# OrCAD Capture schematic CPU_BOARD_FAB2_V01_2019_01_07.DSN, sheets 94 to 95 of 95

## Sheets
94 020 BDX-DE PCIE CPU/PCH: size B
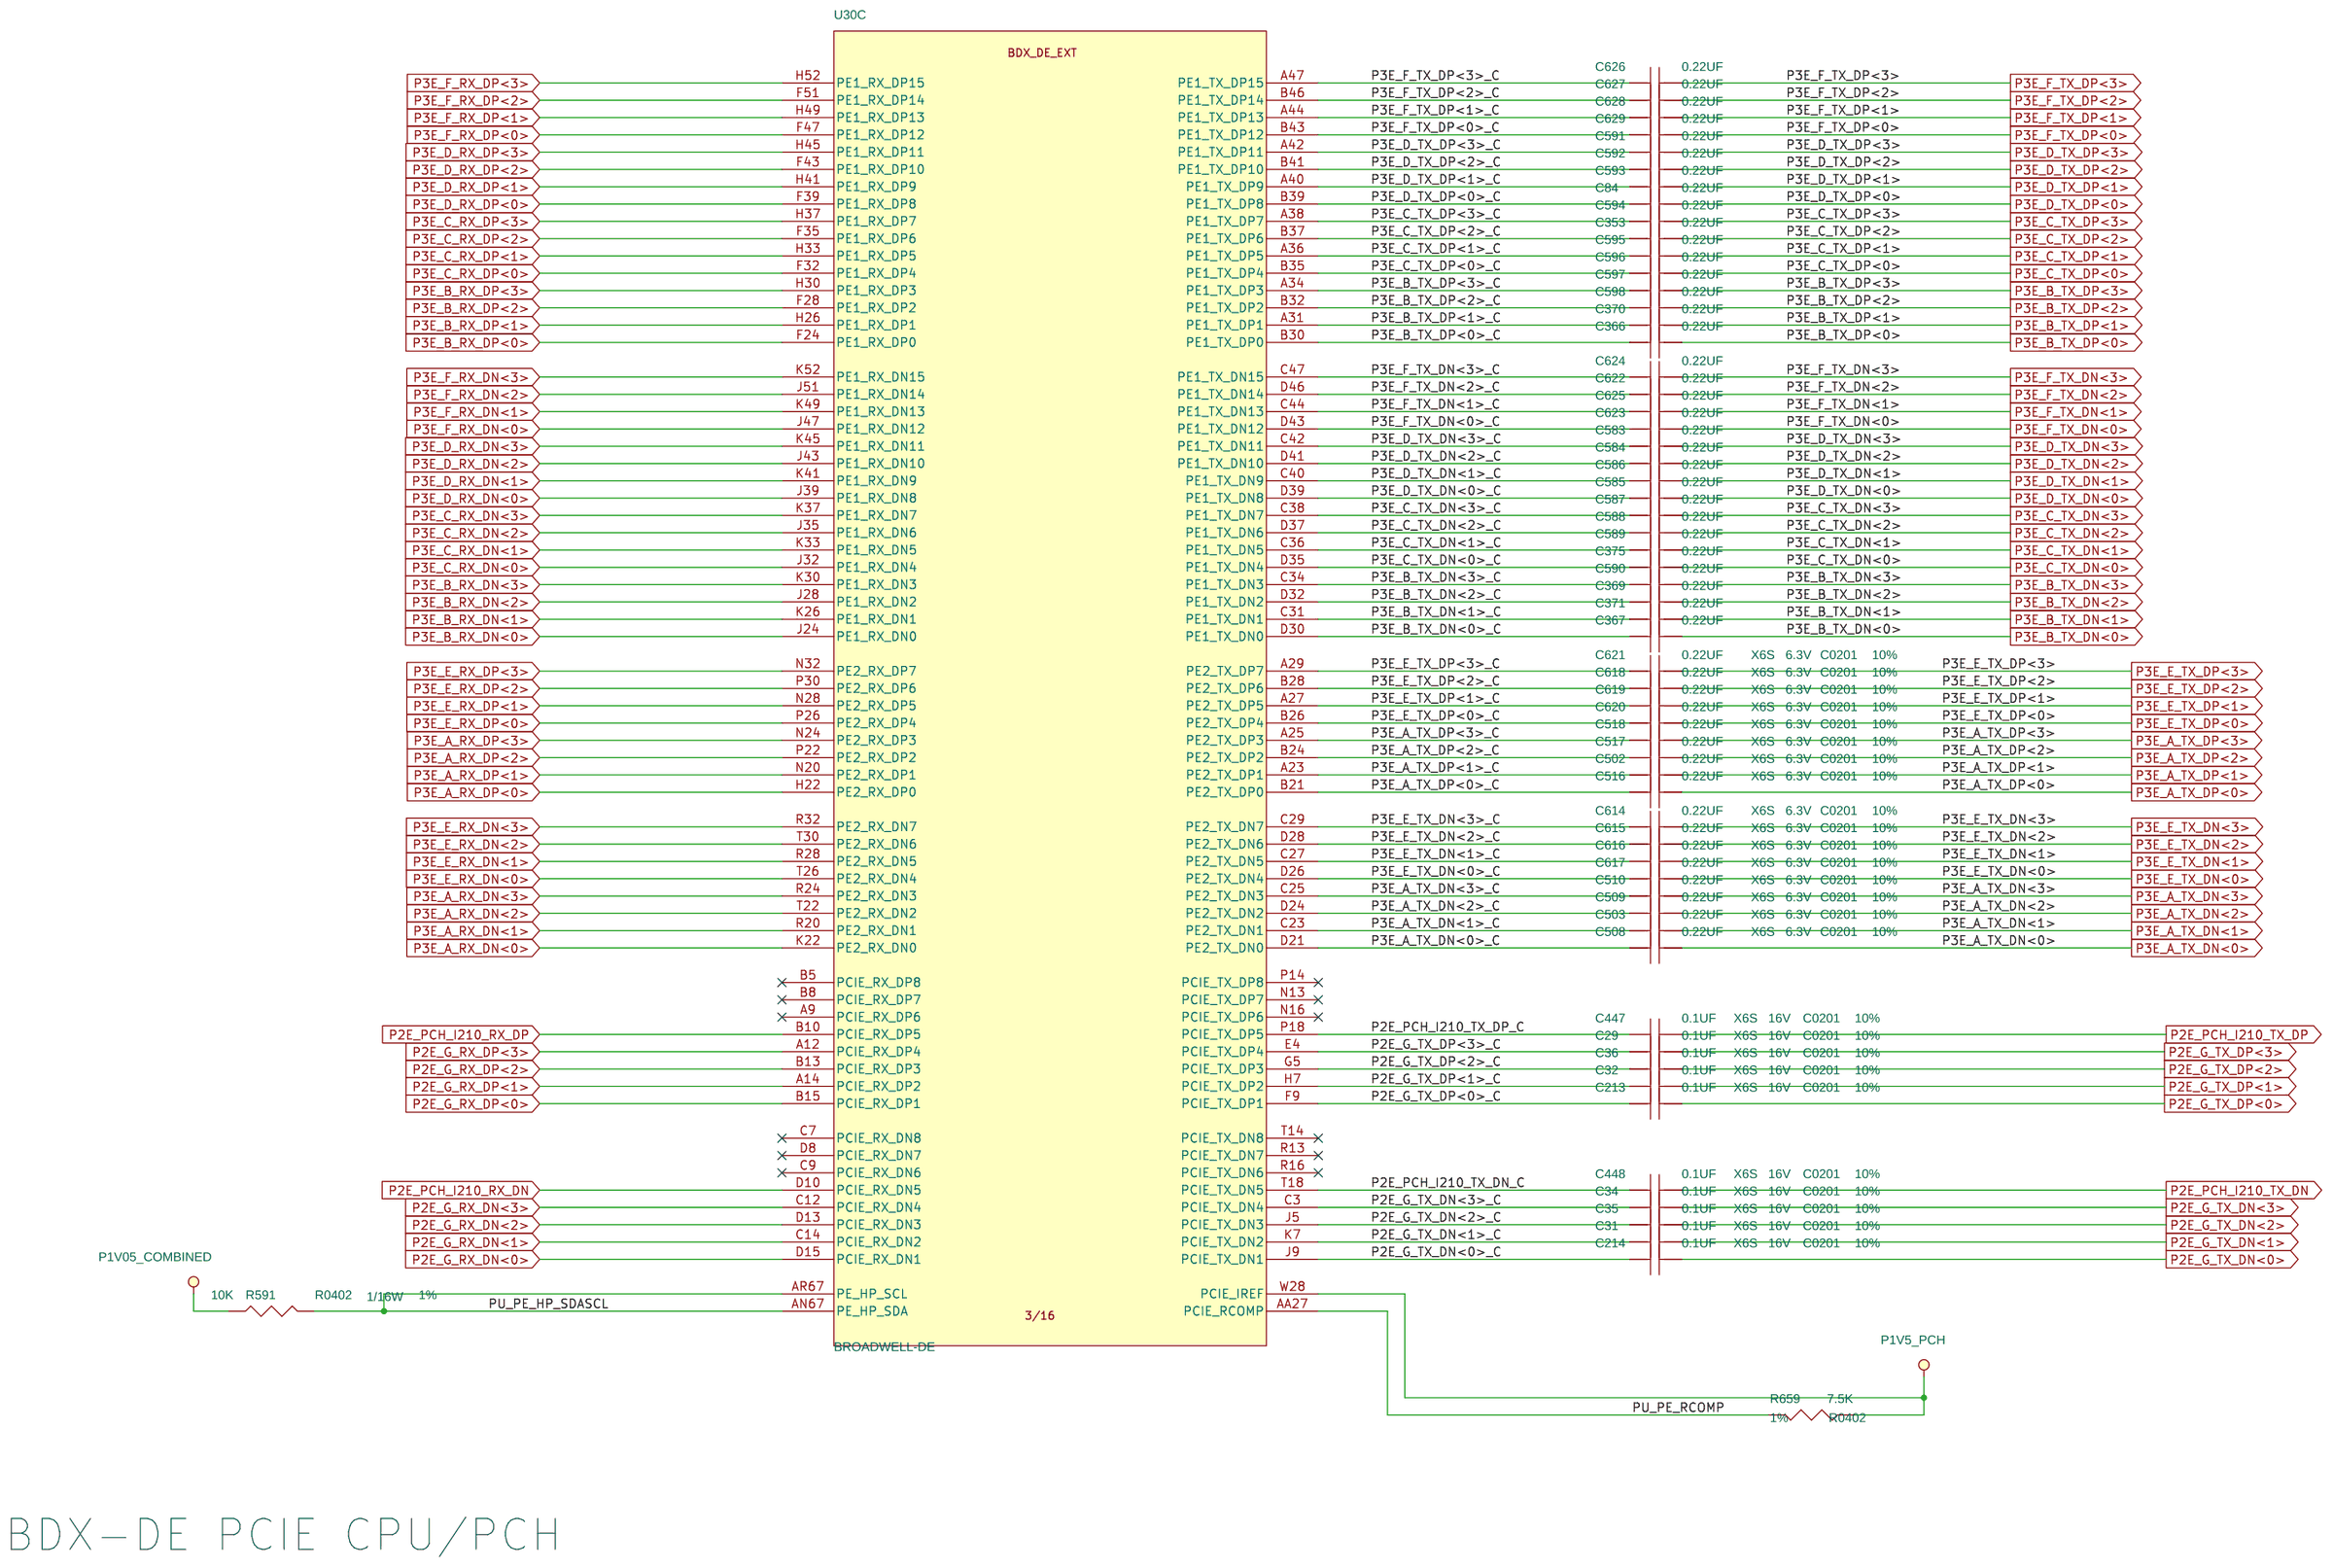
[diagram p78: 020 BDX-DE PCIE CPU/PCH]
95 010 INTERRUPT/ERROR ESCALATION
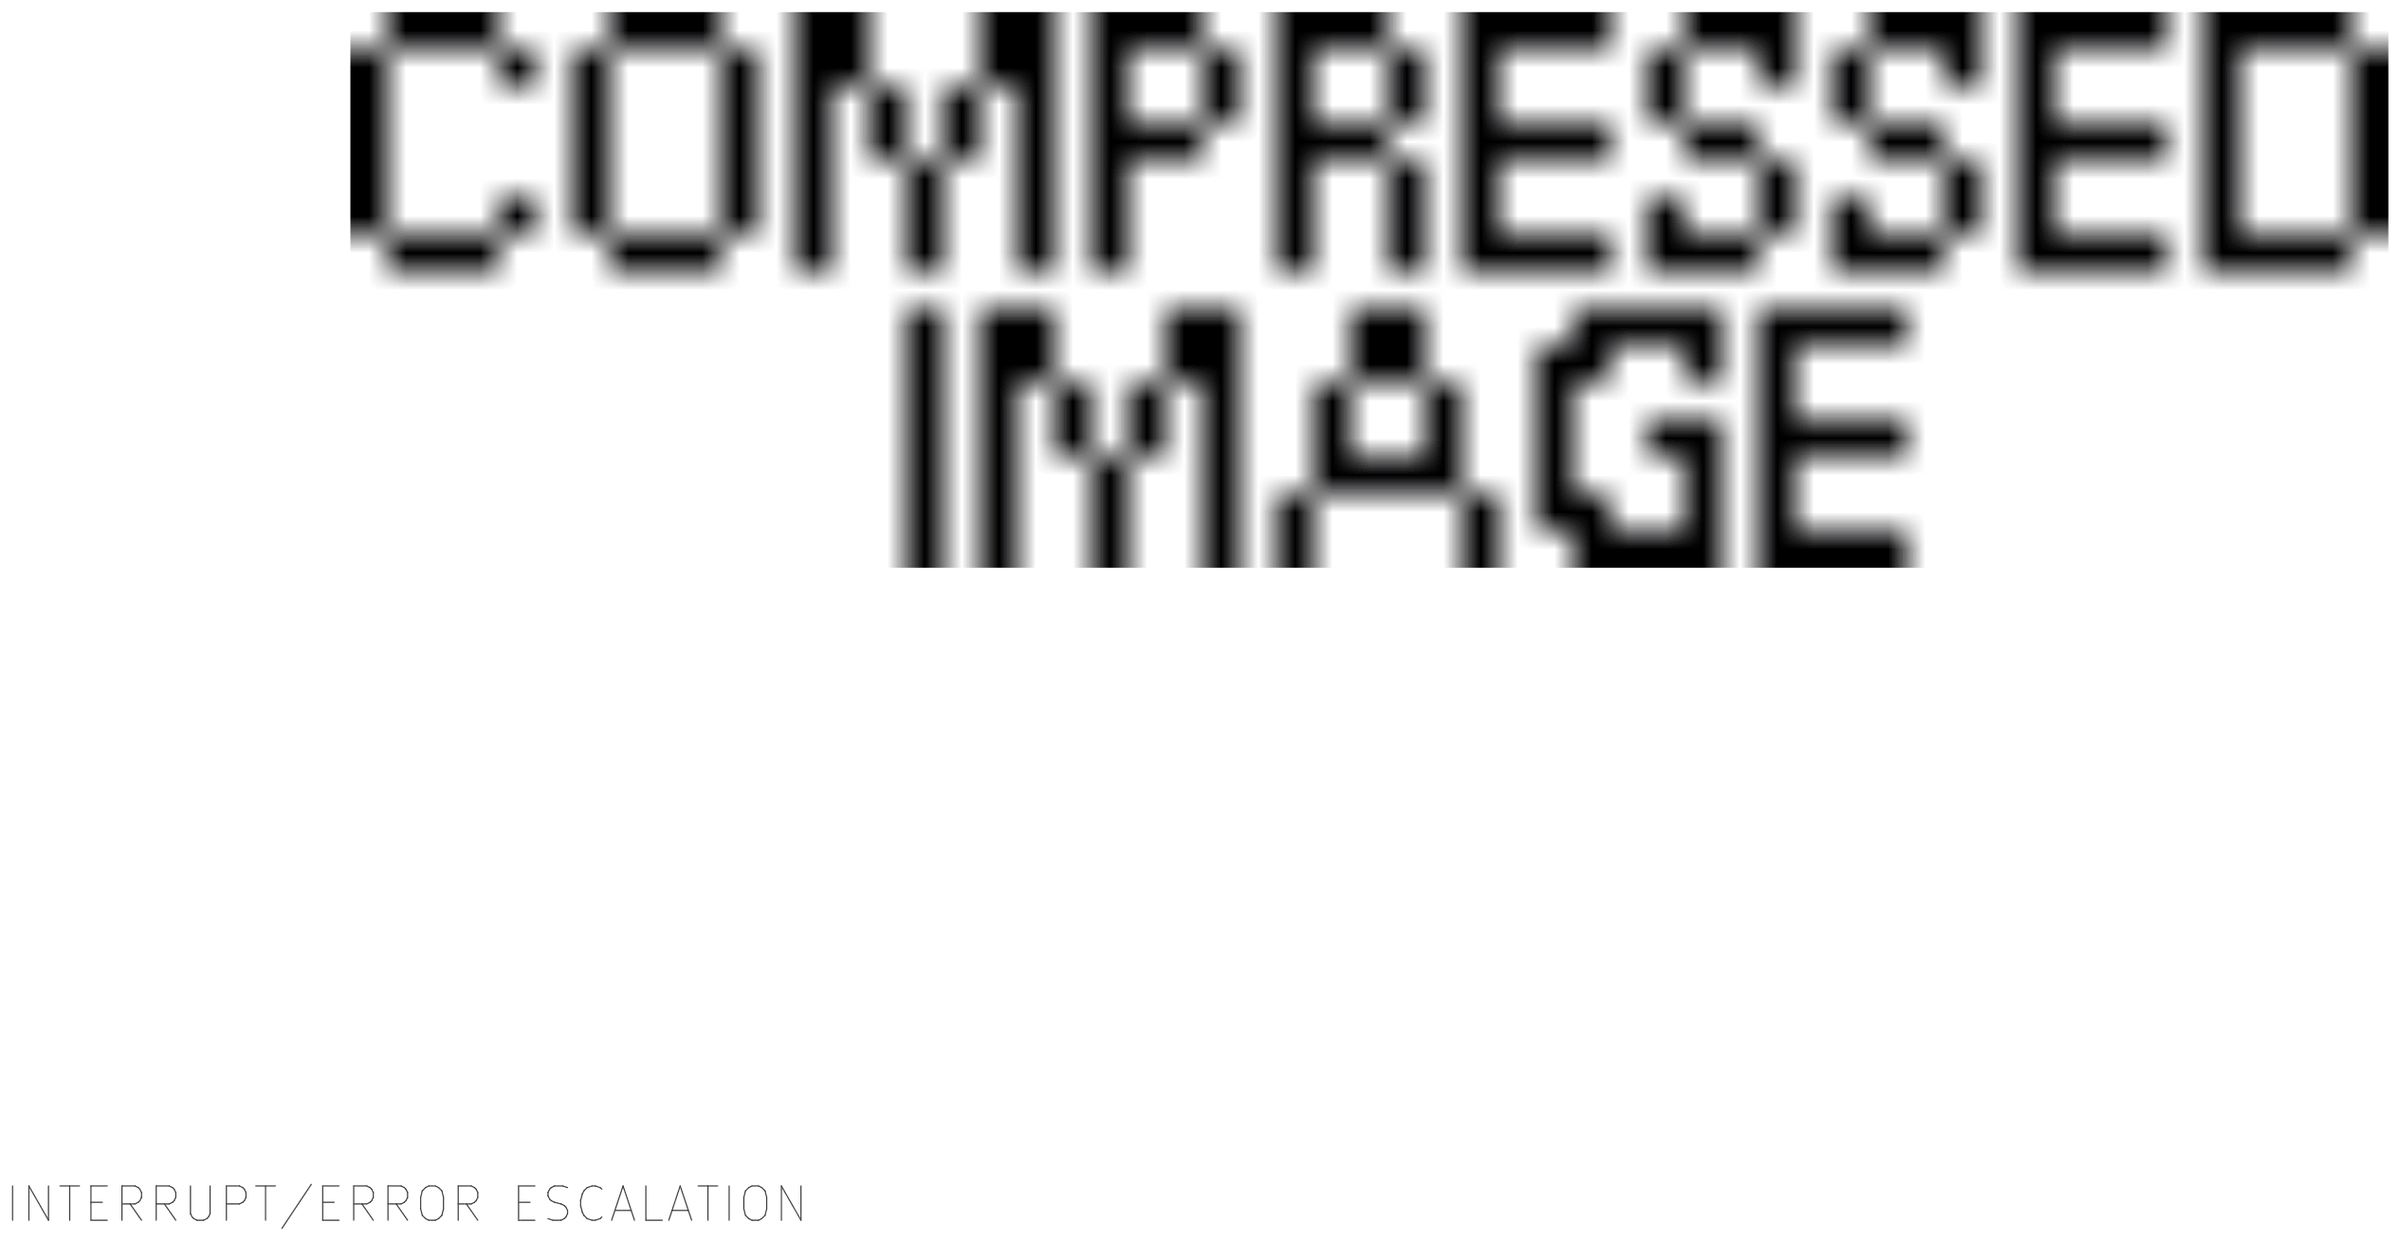
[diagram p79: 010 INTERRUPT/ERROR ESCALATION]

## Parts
sheet 020 BDX-DE PCIE CPU/PCH
C29  0.1UF  [C0201]
C31  0.1UF  [C0201]
C32  0.1UF  [C0201]
C34  0.1UF  [C0201]
C35  0.1UF  [C0201]
C36  0.1UF  [C0201]
C84  0.22UF  [C0201]
C213  0.1UF  [C0201]
C214  0.1UF  [C0201]
C353  0.22UF  [C0201]
C366  0.22UF  [C0201]
C367  0.22UF  [C0201]
C369  0.22UF  [C0201]
C370  0.22UF  [C0201]
C371  0.22UF  [C0201]
C375  0.22UF  [C0201]
C447  0.1UF  [C0201]
C448  0.1UF  [C0201]
C502  0.22UF  [C0201]
C503  0.22UF  [C0201]
C508  0.22UF  [C0201]
C509  0.22UF  [C0201]
C510  0.22UF  [C0201]
C516  0.22UF  [C0201]
C517  0.22UF  [C0201]
C518  0.22UF  [C0201]
C583  0.22UF  [C0201]
C584  0.22UF  [C0201]
C585  0.22UF  [C0201]
C586  0.22UF  [C0201]
C587  0.22UF  [C0201]
C588  0.22UF  [C0201]
C589  0.22UF  [C0201]
C590  0.22UF  [C0201]
C591  0.22UF  [C0201]
C592  0.22UF  [C0201]
C593  0.22UF  [C0201]
C594  0.22UF  [C0201]
C595  0.22UF  [C0201]
C596  0.22UF  [C0201]
C597  0.22UF  [C0201]
C598  0.22UF  [C0201]
C614  0.22UF  [C0201]
C615  0.22UF  [C0201]
C616  0.22UF  [C0201]
C617  0.22UF  [C0201]
C618  0.22UF  [C0201]
C619  0.22UF  [C0201]
C620  0.22UF  [C0201]
C621  0.22UF  [C0201]
C622  0.22UF  [C0201]
C623  0.22UF  [C0201]
C624  0.22UF  [C0201]
C625  0.22UF  [C0201]
C626  0.22UF  [C0201]
C627  0.22UF  [C0201]
C628  0.22UF  [C0201]
C629  0.22UF  [C0201]
R591  10K  [R0402]
R659  7.5K  [R0402]
sheet 023 BDX-DE SATA, USB2, USB3
U30  BROADWELL-DE  [BGA1667]  (sections A,B,C,D,E,F,G,H,I,J,K,L,M,N,O,P)

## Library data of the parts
C29 C31 C32 C34-C36 C213 C214 C447 C448 = CAP_NP: CAP CHIP 0.1UF 16V(+-10%,X6S,0201); CLASS: DISCRETE; CMPLS_LVL: EP(V1); Data: TAY_EMK063AC6104KP.pdf; From_pj: S2P-SEAN; Lifecycle: Comp-Approve; MATERIAL: X6S; Manuf_PN: EMK063AC6104KP-F; Manuf_name: TAIYO YUDEN CO.,LTD; Manuftr: TAY; Part_Type: *LF_C0201; RD_CMPLS_LVL: EP(V1); TOLERANCE: 10%; VOLTAGE: 16V; fp_ECN: DCN-all 0201 RCL part.doc
C84 C353 C366 C367 C369-C371 C375 C502 C503 C508-C510 C516-C518 C583-C598 C614-C629 = CAP_NP: CAP CHIP 0.22UF 6.3V(+-10%,X6S,0201); CLASS: DISCRETE; CMPLS_LVL: EP(V1); Data: MUR_LF_CAPSERIES_19JUN2012.pdf; From_pj: MF1-EDDIE; Lifecycle: Comp-Approve; MATERIAL: X6S; Manuf_PN: GRM033C80J224K; Manuf_name: MURATA ERIE N.A. INC TAIWAN BRANCH Okayama Murata Mfg.Co.,Ltd.Wakura Murata Mfg.; Manuftr: MUR; Part_Type: *LF_C0201; RD_CMPLS_LVL: EP(V1); TOLERANCE: 10%; VOLTAGE: 6.3V; fp_ECN: DCN-all 0201 RCL part.doc
R591 = R: RES CHIP 10K 1/16W +-1% (0402); CLASS: DISCRETE; CMPLS_LVL: EP; Data: WTC_LF_WR SERIES.pdf; From_pj: S82; Lifecycle: Comp-Approve; MATERIAL: CHIP; Manuf_PN: RR0510S-103-FN; Manuf_name: CYNTEC CO.. LTD.; Manuftr: CYN; Part_Type: *LF_Resistor; Status: Preferred; TOLERANCE: 1%; WATTAGE: 1/16W; fp_ECN: 0402 SERIES_LL34.xls
R659 = R: RES CHIP 7.5K 1/16W +-1% (0402); CLASS: DISCRETE; CMPLS_LVL: EP; Data: WTC_LF_WR SERIES-4.pdf; From_pj: S93-MARTIN; MATERIAL: CHIP; Manuf_PN: WR04X7501FTL; Manuf_name: WALSIN TECHNOLOGY CORPORATION; Manuftr: WTC; Part_Type: *LF_Resistor; TOLERANCE: 1%; WATTAGE: 1/16W; fp_ECN: 0402 SERIES_LL34.xls
U30 = BROADWELLDE: CPU(1667P)Broadwell-DE (FCBGA); CLASS: IC; Data: INT_Broadwell-DE_REV0_75.pdf; From_pj: S1M-MANSON; MATERIAL: IC; Manuf_name: INTEGRATED DEVICE TECHNOLOGY,INC.; Manuftr: INT; Part_Type: Tmp; Color: Default; Location X-Coordinate: 0; Location Y-Coordinate: 0; Power Pins Visible: False; Primitive: DEFAULT

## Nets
P1V05_COMBINED: R591.1 ; also on sheet 1 3 4 16 18 19 41 42 45 47 48 50 51 52 54 55 56 63 71 74 75 79 84 92
P1V5_PCH: R659.1 U30.W28(PCIE_IREF) ; also on sheet 31 46 47 49 52
P2E_G_RX_DN<0>: U30.D15(PCIE_RX_DN1) ; also on sheet 13
P2E_G_RX_DN<1>: U30.C14(PCIE_RX_DN2) ; also on sheet 13
P2E_G_RX_DN<2>: U30.D13(PCIE_RX_DN3) ; also on sheet 13
P2E_G_RX_DN<3>: U30.C12(PCIE_RX_DN4) ; also on sheet 13
P2E_G_RX_DP<0>: U30.B15(PCIE_RX_DP1) ; also on sheet 13
P2E_G_RX_DP<1>: U30.A14(PCIE_RX_DP2) ; also on sheet 13
P2E_G_RX_DP<2>: U30.B13(PCIE_RX_DP3) ; also on sheet 13
P2E_G_RX_DP<3>: U30.A12(PCIE_RX_DP4) ; also on sheet 13
P2E_G_TX_DN<0>: C214.2 ; also on sheet 13
P2E_G_TX_DN<0>_C: C214.1 U30.J9(PCIE_TX_DN1)
P2E_G_TX_DN<1>: C31.2 ; also on sheet 13
P2E_G_TX_DN<1>_C: C31.1 U30.K7(PCIE_TX_DN2)
P2E_G_TX_DN<2>: C35.2 ; also on sheet 13
P2E_G_TX_DN<2>_C: C35.1 U30.J5(PCIE_TX_DN3)
P2E_G_TX_DN<3>: C34.2 ; also on sheet 13
P2E_G_TX_DN<3>_C: C34.1 U30.C3(PCIE_TX_DN4)
P2E_G_TX_DP<0>: C213.2 ; also on sheet 13
P2E_G_TX_DP<0>_C: C213.1 U30.F9(PCIE_TX_DP1)
P2E_G_TX_DP<1>: C32.2 ; also on sheet 13
P2E_G_TX_DP<1>_C: C32.1 U30.H7(PCIE_TX_DP2)
P2E_G_TX_DP<2>: C36.2 ; also on sheet 13
P2E_G_TX_DP<2>_C: C36.1 U30.G5(PCIE_TX_DP3)
P2E_G_TX_DP<3>: C29.2 ; also on sheet 13
P2E_G_TX_DP<3>_C: C29.1 U30.E4(PCIE_TX_DP4)
P2E_PCH_I210_RX_DN: U30.D10(PCIE_RX_DN5) ; also on sheet 87
P2E_PCH_I210_RX_DP: U30.B10(PCIE_RX_DP5) ; also on sheet 87
P2E_PCH_I210_TX_DN: C448.2 ; also on sheet 87
P2E_PCH_I210_TX_DN_C: C448.1 U30.T18(PCIE_TX_DN5)
P2E_PCH_I210_TX_DP: C447.2 ; also on sheet 87
P2E_PCH_I210_TX_DP_C: C447.1 U30.P18(PCIE_TX_DP5)
P3E_A_RX_DN<0>: U30.K22(PE2_RX_DN0) ; also on sheet 13
P3E_A_RX_DN<1>: U30.R20(PE2_RX_DN1) ; also on sheet 13
P3E_A_RX_DN<2>: U30.T22(PE2_RX_DN2) ; also on sheet 13
P3E_A_RX_DN<3>: U30.R24(PE2_RX_DN3) ; also on sheet 13
P3E_A_RX_DP<0>: U30.H22(PE2_RX_DP0) ; also on sheet 13
P3E_A_RX_DP<1>: U30.N20(PE2_RX_DP1) ; also on sheet 13
P3E_A_RX_DP<2>: U30.P22(PE2_RX_DP2) ; also on sheet 13
P3E_A_RX_DP<3>: U30.N24(PE2_RX_DP3) ; also on sheet 13
P3E_A_TX_DN<0>: C508.2 ; also on sheet 13
P3E_A_TX_DN<0>_C: C508.1 U30.D21(PE2_TX_DN0)
P3E_A_TX_DN<1>: C503.2 ; also on sheet 13
P3E_A_TX_DN<1>_C: C503.1 U30.C23(PE2_TX_DN1)
P3E_A_TX_DN<2>: C509.2 ; also on sheet 13
P3E_A_TX_DN<2>_C: C509.1 U30.D24(PE2_TX_DN2)
P3E_A_TX_DN<3>: C510.2 ; also on sheet 13
P3E_A_TX_DN<3>_C: C510.1 U30.C25(PE2_TX_DN3)
P3E_A_TX_DP<0>: C516.2 ; also on sheet 13
P3E_A_TX_DP<0>_C: C516.1 U30.B21(PE2_TX_DP0)
P3E_A_TX_DP<1>: C502.2 ; also on sheet 13
P3E_A_TX_DP<1>_C: C502.1 U30.A23(PE2_TX_DP1)
P3E_A_TX_DP<2>: C517.2 ; also on sheet 13
P3E_A_TX_DP<2>_C: C517.1 U30.B24(PE2_TX_DP2)
P3E_A_TX_DP<3>: C518.2 ; also on sheet 13
P3E_A_TX_DP<3>_C: C518.1 U30.A25(PE2_TX_DP3)
P3E_B_RX_DN<0>: U30.J24(PE1_RX_DN0) ; also on sheet 12
P3E_B_RX_DN<1>: U30.K26(PE1_RX_DN1) ; also on sheet 12
P3E_B_RX_DN<2>: U30.J28(PE1_RX_DN2) ; also on sheet 12
P3E_B_RX_DN<3>: U30.K30(PE1_RX_DN3) ; also on sheet 12
P3E_B_RX_DP<0>: U30.F24(PE1_RX_DP0) ; also on sheet 12
P3E_B_RX_DP<1>: U30.H26(PE1_RX_DP1) ; also on sheet 12
P3E_B_RX_DP<2>: U30.F28(PE1_RX_DP2) ; also on sheet 12
P3E_B_RX_DP<3>: U30.H30(PE1_RX_DP3) ; also on sheet 12
P3E_B_TX_DN<0>: C367.2 ; also on sheet 12
P3E_B_TX_DN<0>_C: C367.1 U30.D30(PE1_TX_DN0)
P3E_B_TX_DN<1>: C371.2 ; also on sheet 12
P3E_B_TX_DN<1>_C: C371.1 U30.C31(PE1_TX_DN1)
P3E_B_TX_DN<2>: C369.2 ; also on sheet 12
P3E_B_TX_DN<2>_C: C369.1 U30.D32(PE1_TX_DN2)
P3E_B_TX_DN<3>: C590.2 ; also on sheet 12
P3E_B_TX_DN<3>_C: C590.1 U30.C34(PE1_TX_DN3)
P3E_B_TX_DP<0>: C366.2 ; also on sheet 12
P3E_B_TX_DP<0>_C: C366.1 U30.B30(PE1_TX_DP0)
P3E_B_TX_DP<1>: C370.2 ; also on sheet 12
P3E_B_TX_DP<1>_C: C370.1 U30.A31(PE1_TX_DP1)
P3E_B_TX_DP<2>: C598.2 ; also on sheet 12
P3E_B_TX_DP<2>_C: C598.1 U30.B32(PE1_TX_DP2)
P3E_B_TX_DP<3>: C597.2 ; also on sheet 12
P3E_B_TX_DP<3>_C: C597.1 U30.A34(PE1_TX_DP3)
P3E_C_RX_DN<0>: U30.J32(PE1_RX_DN4) ; also on sheet 12
P3E_C_RX_DN<1>: U30.K33(PE1_RX_DN5) ; also on sheet 12
P3E_C_RX_DN<2>: U30.J35(PE1_RX_DN6) ; also on sheet 12
P3E_C_RX_DN<3>: U30.K37(PE1_RX_DN7) ; also on sheet 12
P3E_C_RX_DP<0>: U30.F32(PE1_RX_DP4) ; also on sheet 12
P3E_C_RX_DP<1>: U30.H33(PE1_RX_DP5) ; also on sheet 12
P3E_C_RX_DP<2>: U30.F35(PE1_RX_DP6) ; also on sheet 12
P3E_C_RX_DP<3>: U30.H37(PE1_RX_DP7) ; also on sheet 12
P3E_C_TX_DN<0>: C375.2 ; also on sheet 12
P3E_C_TX_DN<0>_C: C375.1 U30.D35(PE1_TX_DN4)
P3E_C_TX_DN<1>: C589.2 ; also on sheet 12
P3E_C_TX_DN<1>_C: C589.1 U30.C36(PE1_TX_DN5)
P3E_C_TX_DN<2>: C588.2 ; also on sheet 12
P3E_C_TX_DN<2>_C: C588.1 U30.D37(PE1_TX_DN6)
P3E_C_TX_DN<3>: C587.2 ; also on sheet 12
P3E_C_TX_DN<3>_C: C587.1 U30.C38(PE1_TX_DN7)
P3E_C_TX_DP<0>: C596.2 ; also on sheet 12
P3E_C_TX_DP<0>_C: C596.1 U30.B35(PE1_TX_DP4)
P3E_C_TX_DP<1>: C595.2 ; also on sheet 12
P3E_C_TX_DP<1>_C: C595.1 U30.A36(PE1_TX_DP5)
P3E_C_TX_DP<2>: C353.2 ; also on sheet 12
P3E_C_TX_DP<2>_C: C353.1 U30.B37(PE1_TX_DP6)
P3E_C_TX_DP<3>: C594.2 ; also on sheet 12
P3E_C_TX_DP<3>_C: C594.1 U30.A38(PE1_TX_DP7)
P3E_D_RX_DN<0>: U30.J39(PE1_RX_DN8) ; also on sheet 12
P3E_D_RX_DN<1>: U30.K41(PE1_RX_DN9) ; also on sheet 12
P3E_D_RX_DN<2>: U30.J43(PE1_RX_DN10) ; also on sheet 12
P3E_D_RX_DN<3>: U30.K45(PE1_RX_DN11) ; also on sheet 12
P3E_D_RX_DP<0>: U30.F39(PE1_RX_DP8) ; also on sheet 12
P3E_D_RX_DP<1>: U30.H41(PE1_RX_DP9) ; also on sheet 12
P3E_D_RX_DP<2>: U30.F43(PE1_RX_DP10) ; also on sheet 12
P3E_D_RX_DP<3>: U30.H45(PE1_RX_DP11) ; also on sheet 12
P3E_D_TX_DN<0>: C585.2 ; also on sheet 12
P3E_D_TX_DN<0>_C: C585.1 U30.D39(PE1_TX_DN8)
P3E_D_TX_DN<1>: C586.2 ; also on sheet 12
P3E_D_TX_DN<1>_C: C586.1 U30.C40(PE1_TX_DN9)
P3E_D_TX_DN<2>: C584.2 ; also on sheet 12
P3E_D_TX_DN<2>_C: C584.1 U30.D41(PE1_TX_DN10)
P3E_D_TX_DN<3>: C583.2 ; also on sheet 12
P3E_D_TX_DN<3>_C: C583.1 U30.C42(PE1_TX_DN11)
P3E_D_TX_DP<0>: C84.2 ; also on sheet 12
P3E_D_TX_DP<0>_C: C84.1 U30.B39(PE1_TX_DP8)
P3E_D_TX_DP<1>: C593.2 ; also on sheet 12
P3E_D_TX_DP<1>_C: C593.1 U30.A40(PE1_TX_DP9)
P3E_D_TX_DP<2>: C592.2 ; also on sheet 12
P3E_D_TX_DP<2>_C: C592.1 U30.B41(PE1_TX_DP10)
P3E_D_TX_DP<3>: C591.2 ; also on sheet 12
P3E_D_TX_DP<3>_C: C591.1 U30.A42(PE1_TX_DP11)
P3E_E_RX_DN<0>: U30.T26(PE2_RX_DN4) ; also on sheet 13
P3E_E_RX_DN<1>: U30.R28(PE2_RX_DN5) ; also on sheet 13
P3E_E_RX_DN<2>: U30.T30(PE2_RX_DN6) ; also on sheet 66
P3E_E_RX_DN<3>: U30.R32(PE2_RX_DN7) ; also on sheet 66
P3E_E_RX_DP<0>: U30.P26(PE2_RX_DP4) ; also on sheet 13
P3E_E_RX_DP<1>: U30.N28(PE2_RX_DP5) ; also on sheet 13
P3E_E_RX_DP<2>: U30.P30(PE2_RX_DP6) ; also on sheet 66
P3E_E_RX_DP<3>: U30.N32(PE2_RX_DP7) ; also on sheet 66
P3E_E_TX_DN<0>: C617.2 ; also on sheet 13
P3E_E_TX_DN<0>_C: C617.1 U30.D26(PE2_TX_DN4)
P3E_E_TX_DN<1>: C616.2 ; also on sheet 13
P3E_E_TX_DN<1>_C: C616.1 U30.C27(PE2_TX_DN5)
P3E_E_TX_DN<2>: C615.2 ; also on sheet 66
P3E_E_TX_DN<2>_C: C615.1 U30.D28(PE2_TX_DN6)
P3E_E_TX_DN<3>: C614.2 ; also on sheet 66
P3E_E_TX_DN<3>_C: C614.1 U30.C29(PE2_TX_DN7)
P3E_E_TX_DP<0>: C620.2 ; also on sheet 13
P3E_E_TX_DP<0>_C: C620.1 U30.B26(PE2_TX_DP4)
P3E_E_TX_DP<1>: C619.2 ; also on sheet 13
P3E_E_TX_DP<1>_C: C619.1 U30.A27(PE2_TX_DP5)
P3E_E_TX_DP<2>: C618.2 ; also on sheet 66
P3E_E_TX_DP<2>_C: C618.1 U30.B28(PE2_TX_DP6)
P3E_E_TX_DP<3>: C621.2 ; also on sheet 66
P3E_E_TX_DP<3>_C: C621.1 U30.A29(PE2_TX_DP7)
P3E_F_RX_DN<0>: U30.J47(PE1_RX_DN12) ; also on sheet 12
P3E_F_RX_DN<1>: U30.K49(PE1_RX_DN13) ; also on sheet 12
P3E_F_RX_DN<2>: U30.J51(PE1_RX_DN14) ; also on sheet 12
P3E_F_RX_DN<3>: U30.K52(PE1_RX_DN15) ; also on sheet 12
P3E_F_RX_DP<0>: U30.F47(PE1_RX_DP12) ; also on sheet 12
P3E_F_RX_DP<1>: U30.H49(PE1_RX_DP13) ; also on sheet 12
P3E_F_RX_DP<2>: U30.F51(PE1_RX_DP14) ; also on sheet 12
P3E_F_RX_DP<3>: U30.H52(PE1_RX_DP15) ; also on sheet 12
P3E_F_TX_DN<0>: C623.2 ; also on sheet 12
P3E_F_TX_DN<0>_C: C623.1 U30.D43(PE1_TX_DN12)
P3E_F_TX_DN<1>: C625.2 ; also on sheet 12
P3E_F_TX_DN<1>_C: C625.1 U30.C44(PE1_TX_DN13)
P3E_F_TX_DN<2>: C622.2 ; also on sheet 12
P3E_F_TX_DN<2>_C: C622.1 U30.D46(PE1_TX_DN14)
P3E_F_TX_DN<3>: C624.2 ; also on sheet 12
P3E_F_TX_DN<3>_C: C624.1 U30.C47(PE1_TX_DN15)
P3E_F_TX_DP<0>: C629.2 ; also on sheet 12
P3E_F_TX_DP<0>_C: C629.1 U30.B43(PE1_TX_DP12)
P3E_F_TX_DP<1>: C628.2 ; also on sheet 12
P3E_F_TX_DP<1>_C: C628.1 U30.A44(PE1_TX_DP13)
P3E_F_TX_DP<2>: C627.2 ; also on sheet 12
P3E_F_TX_DP<2>_C: C627.1 U30.B46(PE1_TX_DP14)
P3E_F_TX_DP<3>: C626.2 ; also on sheet 12
P3E_F_TX_DP<3>_C: C626.1 U30.A47(PE1_TX_DP15)
PU_PE_HP_SDASCL: R591.2 U30.AN67(PE_HP_SDA) U30.AR67(PE_HP_SCL)
PU_PE_RCOMP: R659.2 U30.AA27(PCIE_RCOMP)

Not connected (* = marked no-connect by the designer): U30 A9(PCIE_RX_DP6)* B5(PCIE_RX_DP8)* B8(PCIE_RX_DP7)* C7(PCIE_RX_DN8)* C9(PCIE_RX_DN6)* D8(PCIE_RX_DN7)* N13(PCIE_TX_DP7)* N16(PCIE_TX_DP6)* P14(PCIE_TX_DP8)* R13(PCIE_TX_DN7)* R16(PCIE_TX_DN6)* T14(PCIE_TX_DN8)*

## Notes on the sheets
sheet 94
- BDX-DE PCIE CPU/PCH
sheet 95
- INTERRUPT/ERROR ESCALATION
